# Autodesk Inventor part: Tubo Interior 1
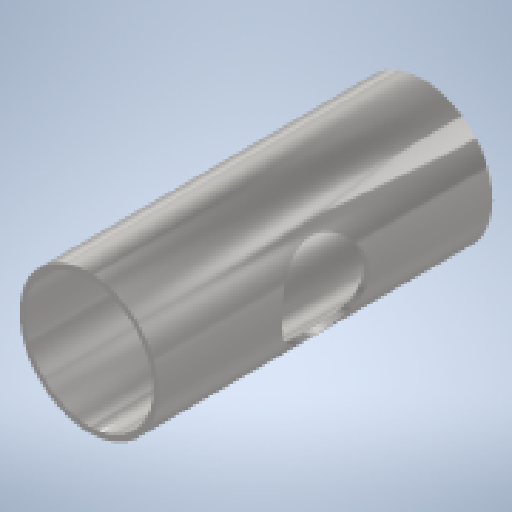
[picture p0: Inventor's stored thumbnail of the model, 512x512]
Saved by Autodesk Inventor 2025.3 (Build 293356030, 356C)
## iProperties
Created: 2025-10
Part Number: Tubo Interior 1
Material: Acero inoxidable
Document SubType Name: Modeling
Designer: Asus
Density: 8 g/cm^3
Appearance: Semipulido
Author: Asus
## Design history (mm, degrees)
sketch "Boceto1"
  geometry: C1 r 36.513 at (0, 0); C2 r 33.462 at (0, 0); 1 further point
  constraints: 2 centre point, 2 coincident
  dimensions: "d0" = 73.025 diameter of C1; "d1" = 3.05 radial gap between concentric circles of C1 C2
extrude "Extrusión1" new body sketch "Boceto1" stored distance "d2" = 175; taper "d3" = 0 deg
sketch "Boceto2"
  geometry: C1 r 23 at (0, 0); 1 further point
  constraints: 1 centre point, 1 coincident
  dimensions: "d4" = 46 diameter of C1
extrude "Extrusión2" cut sketch "Boceto2" extent not by distance; stored distance "d5" = 0; taper "d6" = 0 deg
node "Sólido1"
